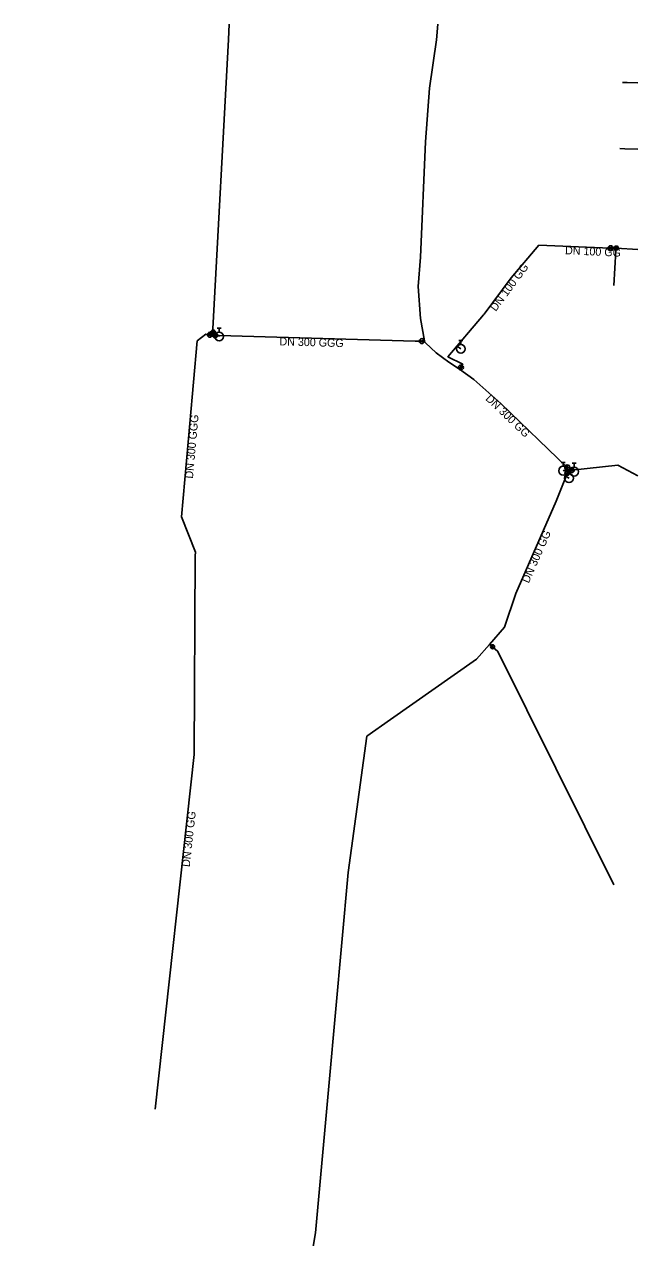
# Model space of a CAD drawing. Extents: x -452548 to -451108, y -1100145 to -1099658.
# Drawn here: x -451231.1 to -451108.1, y -1099901.8 to -1099658.5 of the extents above; entities that cross this region are included whole.
import ezdxf

# ---------------------------------------------------------------- set-up
doc = ezdxf.new("R2010")
doc.units = 0
for name, color, linetype in [('_hydrantova_odbocka_', 7, 'Continuous'), ('_pripojka_prevzato_z_dokumentace_', 7, 'Continuous'), ('_pripojka_priblizne_', 7, 'Continuous'), ('_voda_smvak_prevzato_z_dokumentace_', 7, 'Continuous'), ('_voda_smvak_priblizne_', 7, 'Continuous'), ('Default', 7, 'Continuous'), ('MoLevel 27', 7, 'Continuous'), ('MoLevel 28', 7, 'Continuous'), ('MoLevel 46', 7, 'Continuous'), ('MoLevel 53', 7, 'Continuous')]:
    doc.layers.add(name, color=color, linetype=linetype)

# ---------------------------------------------------------------- blocks, each defined once
blk = doc.blocks.new('_uzaver_')
at = {"layer": 'Default'}
for p, q in [((-0.000035, -0.000035), (0.000035, 0.000035)), ((0.000035, -0.000035), (-0.000035, 0.000035))]:
    blk.add_line(p, q, dxfattribs=at)
for radius in [0.00005, 0.0000025]:
    blk.add_circle((0, 0), radius, dxfattribs=at)
blk = doc.blocks.new('_uzaver_pripojka_')
at = {"layer": 'Default'}
for p, q in [((-0.000035, -0.000035), (0.000035, 0.000035)), ((0.000035, -0.000035), (-0.000035, 0.000035))]:
    blk.add_line(p, q, dxfattribs=at)
for radius in [0.00005, 0.0000025]:
    blk.add_circle((0, 0), radius, dxfattribs=at)
blk = doc.blocks.new('_hydrant_voda_')
at = {"layer": 'Default'}
for p, q in [((-0.000023, 0.000095), (0.000023, 0.000095)), ((0, 0.000095), (0, 0.00005))]:
    blk.add_line(p, q, dxfattribs=at)
blk.add_circle((0, 0), 0.00005, dxfattribs=at)

msp = doc.modelspace()

# ---------------------------------------------------------------- linework, layer by layer
at = {"layer": '_hydrantova_odbocka_'}
for p, q in [((-451191.99, -1099720.89), (-451192, -1099721.05)), ((-451144.32, -1099722.98), (-451143.55, -1099723.54)), ((-451122.59, -1099747.81), (-451123.05, -1099747.97)), ((-451121.05, -1099747.82), (-451120.84, -1099748.16)), ((-451122.45, -1099749.11), (-451121.86, -1099749.47))]:
    msp.add_line(p, q, dxfattribs=at)
at = {"layer": '_pripojka_prevzato_z_dokumentace_'}
for p, q in [((-451110.23, -1099670.15), (-451111.14, -1099670.12)), ((-451108.09, -1099670.21), (-451110.23, -1099670.15)), ((-451110.67, -1099683.43), (-451111.7, -1099683.39)), ((-451108.09, -1099683.53), (-451110.67, -1099683.43))]:
    msp.add_line(p, q, dxfattribs=at)
msp.add_lwpolyline([(-451112.39, -1099703.33), (-451112.44, -1099703.56), (-451112.47, -1099703.88), (-451112.88, -1099710.86)], dxfattribs=at)
at = {"layer": '_pripojka_priblizne_'}
msp.add_lwpolyline([(-451137.82, -1099782.79), (-451137.19, -1099783.25), (-451136.11, -1099784.21), (-451112.88, -1099831.03)], dxfattribs=at)
at = {"layer": '_voda_smvak_prevzato_z_dokumentace_'}
for p, q in [((-451113.53, -1099703.37), (-451127.93, -1099702.72)), ((-451193.87, -1099720.72), (-451193.28, -1099720.8)), ((-451193.28, -1099720.8), (-451193.22, -1099720.25)), ((-451193.28, -1099720.8), (-451192.81, -1099720.86)), ((-451151.38, -1099721.99), (-451150.84, -1099721.95)), ((-451122.04, -1099747.92), (-451122.59, -1099747.81)), ((-451122.21, -1099747.3), (-451122.04, -1099747.92)), ((-451122.04, -1099747.92), (-451122.19, -1099748.39)), ((-451121.3, -1099747.85), (-451122.04, -1099747.92))]:
    msp.add_line(p, q, dxfattribs=at)
for points in [[(-451193.22, -1099720.25), (-451193.25, -1099719.53), (-451190.11, -1099661.53), (-451189.97, -1099658.46)], [(-451150.84, -1099721.95), (-451151.66, -1099717.46), (-451152.09, -1099711.01), (-451151.67, -1099705.16), (-451150.62, -1099682.04), (-451149.86, -1099671.27), (-451148.42, -1099661.61), (-451148.19, -1099658.46)], [(-451127.93, -1099702.72), (-451133.49, -1099709.3), (-451138.87, -1099716.56), (-451138.98, -1099716.7)], [(-451108.09, -1099703.61), (-451112.39, -1099703.33), (-451113.53, -1099703.37)], [(-451196.8, -1099765.02), (-451196.75, -1099764.29), (-451199.56, -1099757.24), (-451197.89, -1099738.52), (-451196.42, -1099721.94), (-451194.65, -1099720.61), (-451193.87, -1099720.72)], [(-451192.81, -1099720.86), (-451192.4, -1099720.87), (-451191.99, -1099720.89)], [(-451191.99, -1099720.89), (-451152.71, -1099721.99), (-451151.38, -1099721.99)], [(-451143.81, -1099727.62), (-451145.93, -1099726.2), (-451148.51, -1099724.34), (-451150.65, -1099722.34), (-451150.8, -1099722.2), (-451150.84, -1099721.95)], [(-451143.81, -1099727.62), (-451140.92, -1099729.69), (-451135.54, -1099734.49), (-451122.21, -1099747.3)], [(-451108.09, -1099749.01), (-451112.08, -1099746.83), (-451121.3, -1099747.85)], [(-451122.19, -1099748.39), (-451124.45, -1099754.09), (-451132.55, -1099772.57), (-451134.78, -1099779.33)], [(-451204.86, -1099875.99), (-451197.03, -1099804.85), (-451196.8, -1099765.02)], [(-451231.08, -1100145.05), (-451227.93, -1100134.42), (-451219.58, -1100105.57), (-451211.31, -1100076.73), (-451202.65, -1100047.88), (-451194.93, -1100019.1), (-451188.68, -1099989.6), (-451182.75, -1099960.08), (-451172.72, -1099900.77), (-451169.95, -1099870.63), (-451166.16, -1099828.52), (-451162.41, -1099801.21), (-451157.67, -1099797.88), (-451140.42, -1099785.75), (-451137.82, -1099782.79), (-451134.78, -1099779.33)]]:
    msp.add_lwpolyline(points, dxfattribs=at)
at = {"layer": '_voda_smvak_priblizne_'}
msp.add_line((-451143.54, -1099727.29), (-451143.81, -1099727.62), dxfattribs=at)
msp.add_lwpolyline([(-451138.98, -1099716.7), (-451146.15, -1099725.13), (-451143.17, -1099726.62), (-451143.54, -1099727.29)], dxfattribs=at)

# ---------------------------------------------------------------- block references
at = {"layer": 'MoLevel 27'}
for p, xscale, yscale, rotation in [((-451113.53, -1099703.37), 10000.000000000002, 10000, 7.903765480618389), ((-451193.87, -1099720.72), 10000.000000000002, 10000, -8.027238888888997), ((-451193.22, -1099720.25), 9999.999999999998, 10000, 83.57215), ((-451192.81, -1099720.86), 10000, 10000, -7.5238194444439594), ((-451151.38, -1099721.99), 9999.999999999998, 9999.999999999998, 179.990387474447), ((-451143.54, -1099727.29), 9999.999999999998, 9999.999999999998, 61.064952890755), ((-451122.21, -1099747.3), 10000, 10000.000000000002, 136.113376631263), ((-451122.19, -1099748.39), 10000, 9999.999999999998, -111.64984254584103), ((-451121.3, -1099747.85), 10000, 10000, 6.32545549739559)]:
    msp.add_blockref('_uzaver_', p, dxfattribs=dict(at, xscale=xscale, yscale=yscale, rotation=rotation))
at = {"layer": 'MoLevel 28', "xscale": 17636.68430335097, "yscale": 17636.68430335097}
for p in [(-451192, -1099721.05), (-451143.55, -1099723.54), (-451123.05, -1099747.97), (-451121.86, -1099749.47), (-451120.84, -1099748.16)]:
    msp.add_blockref('_hydrant_voda_', p, dxfattribs=at)
at = {"layer": 'MoLevel 53', "xscale": 7999.999999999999, "yscale": 7999.999999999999}
for p in [(-451112.39, -1099703.33), (-451137.19, -1099783.25)]:
    msp.add_blockref('_uzaver_pripojka_', p, dxfattribs=at)

# ---------------------------------------------------------------- texts
at = {"layer": 'MoLevel 46'}
for s, rotation, p in [('DN 100 GG', 357.4155, (-451122.69, -1099704.56)), ('DN 100 GG', 53.4598, (-451136.56, -1099716.14)), ('DN 300 GGG', 358.3911, (-451179.94, -1099722.83)), ('DN 300 GG', 316.1396, (-451138.71, -1099733.67)), ('DN 300 GGG', 84.9022, (-451197.27, -1099749.6)), ('DN 300 GG', 66.3316, (-451129.95, -1099770.64)), ('DN 300 GG', 83.7231, (-451197.91, -1099827.48))]:
    msp.add_text(s, height=1.605, rotation=rotation, dxfattribs=at).set_placement(p)

doc.saveas('drawing.dxf')
